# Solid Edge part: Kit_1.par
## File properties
Sűrűség: 0,000 kg/m^3
Pontosság: 0,990
Author: ahadarics
Last saved by: psaghy
Revision: 78
Username: ahadarics
Dokumentum tartalom típus: 0
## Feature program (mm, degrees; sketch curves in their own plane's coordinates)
base feature "unnamed BaseFeature 1"
sketch for "Furat_1" plane through (0, 0, 39) normal (0, 0, 1) x-axis (0, -1, 0)
  hole centre (-23.25, -23.25) bore radius 3.3235
hole "Furat_1" nominal diameter 8 finite  VBottomAngle = 118 deg
sketch for "unnamed Hole 1" plane through (0, 0, 39) normal (0, 0, 1) x-axis (0, -1, 0)
  hole centre (-23.25, 23.25) bore radius 3.3235
hole "unnamed Hole 1" finite
sketch for "unnamed Hole 2" plane through (0, 0, 39) normal (0, 0, 1) x-axis (0, -1, 0)
  hole centre (23.25, 23.25) bore radius 3.3235
hole "unnamed Hole 2" finite
sketch for "unnamed Hole 3" plane through (0, 0, 39) normal (0, 0, 1) x-axis (0, -1, 0)
  hole centre (23.25, -23.25) bore radius 3.3235
hole "unnamed Hole 3" finite
pattern "unnamed Pattern 1" of "Furat_1", "unnamed Hole 1", "unnamed Hole 2", "unnamed Hole 3"
sketch for "Furat_5" plane through (32.5, 0.0003, 21.2488) normal (1, 0, 0) x-axis (0, 0, 1)
hole "Furat_5" diameter 13.157 finite  ThreadDepth = 10 mm
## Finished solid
Body 1: solid body, 411 faces, 942 edges, 585 vertices, 7 internal voids.
  Faces by surface: plane 146, cylinder 129, torus 46, cone 37, sphere 23, spline 21, swept 9
  Edges by curve: line 347, curve on surface 286, circle 284, spline 25
Bounding box of the edges (mm; curved faces can reach further): 65.000 x 65.000 x 35.000, from (-32.5, -32.5, 8) to (32.5002, 32.5, 43).
Cylindrical faces by radius (mm): R0.3125 x1, R0.3838 x1, R0.4089 x1, R0.4253 x1, R0.4408 x1, R0.5 x8, R0.5003 x1, R0.5483 x1, R0.5961 x1, R0.615 x1, R0.6311 x1, R0.6362 x1, R0.652 x1, R0.6792 x1, R0.73 x1, R0.7378 x1, R0.7396 x1, R0.9114 x1, R1 x20, R1.0004 x7, R1.001 x6, R1.0014 x8, R1.0015 x1, R1.0026 x1, R1.0394 x1, R1.0539 x1, R1.0734 x1, R1.0987 x1, R1.1871 x1, R1.2561 x1, R1.2722 x2, R1.3621 x1, R1.3711 x1, R1.4 x1, R1.7143 x1, R3.3235 x8, R4 x4, R4.15 x4, R4.5 x1, R5 x2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
Conical faces (half-angle, radius in mm at the cone's reference point): 0.5 deg R18.5 x4, 0.5 deg R22.25 x4, 30 deg R5.1443 x1, 30 deg R11.8557 x1, 31.4296 deg R28.625 x4, 45 deg R2.75 x1, 45 deg R2.825 x1, 45 deg R4.3 x8, 45 deg R6.35 x8, 45 deg R6.72 x1, 59 deg R3.3235 x4
Toroidal faces (ring radius, tube radius in mm): R0.4909 r0.5044 x1, R0.5094 r0.5004 x1, R0.8674 r0.5067 x1, R1.4976 r0.5003 x6, R4.3 r0.3 x4, R4.7 r0.3 x1, R6.45 r0.2 x4, R7.15 r0.5 x4, R9.5 r0.5 x1, R9.75 r0.5 x2, R13.9897 r0.5062 x1, R19.4739 r1 x1, R19.4913 r1 x3, R19.5 r0.5 x1, R20.5 r0.5 x1, R21.2587 r1 x3, R21.2761 r1 x1, R27.25 r1 x3, R31.75 r1 x6, R33.3108 r1 x1
Spherical faces by radius (mm): R0.5 x1, R1 x22
Planar faces by outward normal: +x 23, +y 9, +z 31, -x 5, -y 8, -z 21, oblique 49
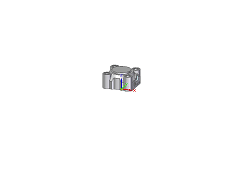
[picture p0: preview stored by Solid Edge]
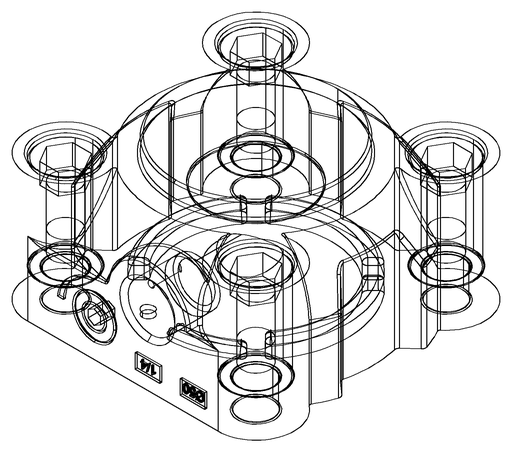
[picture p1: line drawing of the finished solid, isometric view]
